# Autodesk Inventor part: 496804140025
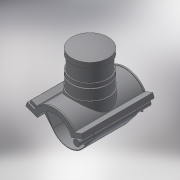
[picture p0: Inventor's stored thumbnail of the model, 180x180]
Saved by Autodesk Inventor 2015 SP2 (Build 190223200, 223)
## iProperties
Created: 2017-07
Part Number: 496804140025
Material: Generic
Description: PLASSON BALLOON SADDLE 140-2.1/2"
Document SubType Name: Modeling
Designer: KIM
Density: 1 g/cm^3
Appearance: Default
Author: KIM
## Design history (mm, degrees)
derived "496804.ipt"
feature "Solid1::496804.ipt"
feature "Solid2::496804.ipt"
tag "TaggingFeature1"
body "Solid1"
body "Solid2"
other parameters: "d1" = 161, "d4" = 176, "d5" = 0, "d40" = 83.72, "d96" = 164.22, "d97" = 3.52, "d98" = 0, "d120" = 140 deg, "d121" = 24.228, "d122" = 20 deg, "d123" = 322, "d124" = 96.6, "d126" = 0, "d143" = 144.2, "d145" = 16.15385, "d149" = 2.1, "d150" = 17.76923, "d153" = 176, "d154" = 0, "d159" = 4.2, "d161" = 2.1, "d162" = 105.6, "d163" = 0, "d168" = 80.5, "d170" = 2.1, "d172" = 0, "d173" = 1, "d176" = 20 deg, "d177" = 11.2, "d180" = 0, "d185" = 57.2, "d186" = 57.2, "d187" = 80.5, "d188" = 6.3, "d190" = 0, "d191" = 128.8, "d193" = 4.2, "d194" = 4.4, "d195" = 90 deg, "d197" = 0, "d199" = 0, "d200" = 105, "d201" = 1, "d203" = 94.5, "d204" = 97.65, "d205" = 85.5, "d206" = 1.8, "d207" = 52.5, "d208" = 42, "d209" = 84, "d210" = 15.75, "d214" = 161, "d216" = 0, "d217" = 87, "d218" = 18, "d219" = 7, "d220" = 15.98, "d221" = 8 deg, "d223" = 8.99272, "d224" = 4.49636, "d226" = 0, "d227" = -17.6, "d228" = 2.1, "d229" = 30.8, "B_" = 174, "H_" = 105, "L_" = 176, "d_t" = 6, "d148" = 2.1, "d160" = 2.1, "d169" = 2.1, "d192" = 4.2, "d222" = 11.24091
